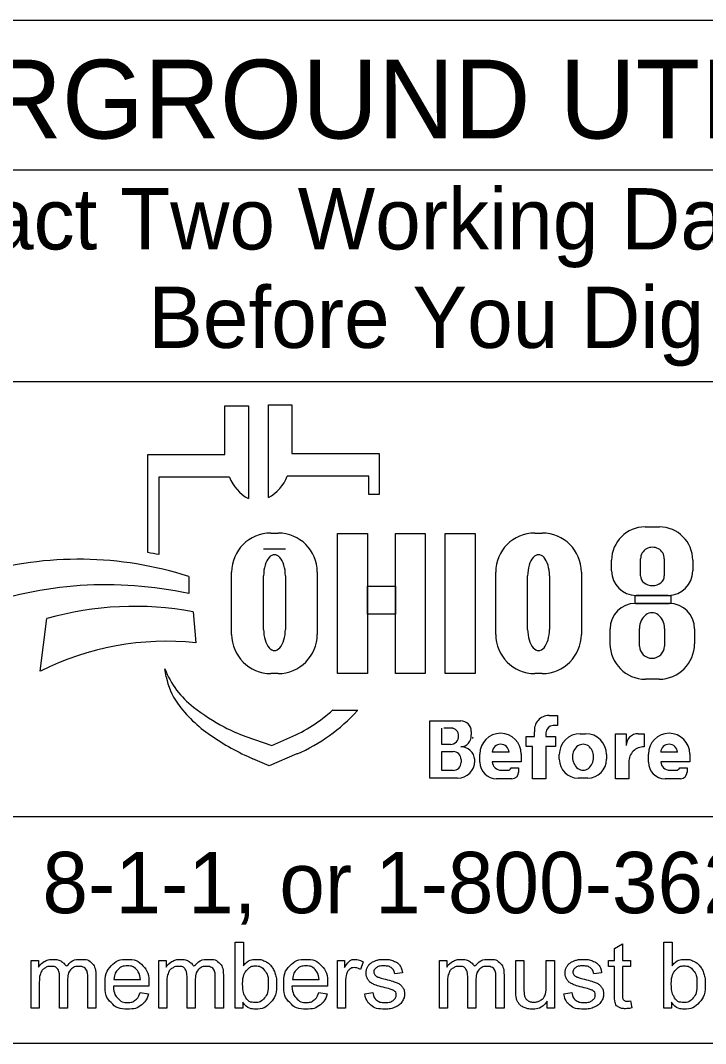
# Model space of a CAD drawing. Extents: x 0 to 34, y 0 to 22.
# Drawn here: x 15.596 to 17.16, y 5.709 to 8.047 of the extents above; entities that cross this region are included whole.
import ezdxf

# ---------------------------------------------------------------- set-up
doc = ezdxf.new("R2010")
doc.units = 0
doc.layers.add('SH_Data', color=7, linetype='Continuous')
doc.layers.add('SH_Text', color=7, linetype='Continuous')

msp = doc.modelspace()

# ---------------------------------------------------------------- linework, layer by layer
at = {"layer": 'SH_Data'}
for p, q in [((18.9567, 8.0466), (14.7067, 8.0466)), ((14.7067, 7.7051), (18.9567, 7.7051)), ((14.7067, 7.2217), (18.9567, 7.2217)), ((18.9567, 6.227), (14.7067, 6.227)), ((18.9567, 5.7091), (14.7067, 5.7091))]:
    msp.add_line(p, q, dxfattribs=at)
at = {"layer": 'SH_Text'}
for p, q in [((16.0627, 7.0547), (16.0627, 7.1661)), ((16.0627, 7.1661), (16.1163, 7.1661)), ((16.1163, 7.1661), (16.1163, 6.9541)), ((16.162, 6.9564), (16.162, 7.1685)), ((16.162, 7.1685), (16.2157, 7.1685)), ((16.2157, 7.1685), (16.2157, 7.057)), ((15.8867, 6.8308), (15.8867, 7.0547)), ((15.8867, 7.0547), (16.0627, 7.0547)), ((16.2157, 7.057), (16.4149, 7.057)), ((16.4149, 7.057), (16.4149, 6.9632)), ((15.912, 7.0032), (15.912, 6.8264)), ((16.0731, 7.0032), (15.912, 7.0032)), ((16.3916, 7.0055), (16.2052, 7.0055)), ((16.3916, 6.9632), (16.3916, 7.0055)), ((16.4149, 6.9632), (16.3916, 6.9632)), ((16.1677, 6.8755), (16.1842, 6.8755)), ((16.7707, 6.8755), (16.7873, 6.8755)), ((17.0223, 6.8895), (17.055, 6.8895)), ((16.201, 6.8385), (16.1512, 6.8385)), ((16.946, 6.7889), (16.946, 6.8132)), ((17.0121, 6.7775), (17.0121, 6.8168)), ((17.0663, 6.8168), (17.0663, 6.7775)), ((17.1313, 6.8132), (17.1313, 6.7889)), ((16.0782, 6.644), (16.0782, 6.786)), ((16.2737, 6.786), (16.2737, 6.644)), ((16.6813, 6.644), (16.6813, 6.786)), ((16.8768, 6.786), (16.8768, 6.644)), ((15.9801, 6.7761), (15.9801, 6.7373)), ((16.1511, 6.6554), (16.1511, 6.7777)), ((16.2009, 6.7777), (16.2009, 6.6554)), ((16.7542, 6.6554), (16.7542, 6.7777)), ((16.804, 6.7777), (16.804, 6.6554)), ((17.0753, 6.7329), (17.002, 6.7329)), ((17.0002, 6.7146), (17.0775, 6.7146)), ((15.99, 6.6955), (15.9962, 6.6245)), ((15.6412, 6.5599), (15.6559, 6.6801)), ((16.9423, 6.6226), (16.9423, 6.6567)), ((17.0098, 6.6167), (17.0098, 6.6576)), ((17.0666, 6.6576), (17.0666, 6.6167)), ((17.1354, 6.6567), (17.1354, 6.6226)), ((15.9289, 6.547), (15.9259, 6.565)), ((16.1842, 6.5545), (16.1677, 6.5545)), ((16.7873, 6.5545), (16.7707, 6.5545)), ((17.0544, 6.5417), (17.0232, 6.5417)), ((16.3092, 6.4712), (16.3666, 6.4712)), ((16.8031, 6.4589), (16.8225, 6.4589)), ((16.8225, 6.4589), (16.8225, 6.4359)), ((16.5305, 6.3154), (16.5305, 6.4461)), ((16.5305, 6.4461), (16.6017, 6.4461)), ((16.5585, 6.3926), (16.5585, 6.4296)), ((16.5837, 6.4296), (16.5624, 6.4296)), ((16.8225, 6.4355), (16.8124, 6.4355)), ((16.1108, 6.4108), (16.1702, 6.3903)), ((16.1702, 6.3903), (16.2112, 6.4081)), ((16.6254, 6.4224), (16.6254, 6.4145)), ((16.7505, 6.3876), (16.7505, 6.4105)), ((16.7505, 6.4105), (16.7698, 6.4105)), ((16.7698, 6.4105), (16.7698, 6.421)), ((16.7959, 6.419), (16.7959, 6.4105)), ((16.7959, 6.4105), (16.8175, 6.4105)), ((16.8175, 6.4105), (16.8175, 6.3876)), ((16.8743, 6.4171), (16.8864, 6.4171)), ((16.9545, 6.3142), (16.9545, 6.4169)), ((16.9545, 6.4169), (16.9791, 6.4169)), ((16.9791, 6.4169), (16.9791, 6.39)), ((17.0063, 6.4169), (17.0202, 6.4169)), ((17.0202, 6.4169), (17.0202, 6.3872)), ((16.5779, 6.3926), (16.5585, 6.3926)), ((16.7654, 6.3876), (16.7505, 6.3876)), ((16.7654, 6.3142), (16.7654, 6.3876)), ((16.8175, 6.3876), (16.7959, 6.3876)), ((16.7959, 6.3876), (16.7959, 6.3142)), ((16.1642, 6.3433), (16.1268, 6.3597)), ((16.2274, 6.3707), (16.1642, 6.3433)), ((16.5585, 6.3332), (16.5585, 6.3761)), ((16.5585, 6.3761), (16.584, 6.3761)), ((16.645, 6.3522), (16.645, 6.3706)), ((16.7116, 6.3746), (16.6731, 6.3746)), ((16.7396, 6.3706), (16.7396, 6.3529)), ((16.8265, 6.3585), (16.8265, 6.3693)), ((16.9342, 6.3693), (16.9342, 6.3585)), ((17.03, 6.3522), (17.03, 6.3706)), ((17.0965, 6.3746), (17.058, 6.3746)), ((17.1245, 6.3706), (17.1245, 6.3529)), ((16.6021, 6.358), (16.6021, 6.3516)), ((16.6335, 6.3551), (16.6335, 6.3547)), ((16.7396, 6.3529), (16.6731, 6.3529)), ((16.7168, 6.3392), (16.7336, 6.3392)), ((16.7336, 6.3392), (16.7336, 6.3294)), ((16.9851, 6.3523), (16.9851, 6.3142)), ((17.1245, 6.3529), (17.0581, 6.3529)), ((17.1017, 6.3392), (17.1186, 6.3392)), ((17.1186, 6.3392), (17.1186, 6.3294)), ((16.5942, 6.3154), (16.5305, 6.3154)), ((16.5837, 6.3332), (16.5585, 6.3332)), ((16.7184, 6.3142), (16.683, 6.3142)), ((16.6941, 6.3337), (16.7082, 6.3337)), ((16.7959, 6.3142), (16.7654, 6.3142)), ((16.8915, 6.3157), (16.8693, 6.3157)), ((16.9851, 6.3142), (16.9545, 6.3142)), ((17.1033, 6.3142), (17.0679, 6.3142)), ((17.079, 6.3337), (17.0931, 6.3337))]:
    msp.add_line(p, q, dxfattribs=at)
for points in [[(16.3201, 6.8744), (16.3881, 6.8744), (16.3881, 6.5544), (16.3201, 6.5544)], [(16.4523, 6.8744), (16.5202, 6.8744), (16.5202, 6.5544), (16.4523, 6.5544)], [(16.5656, 6.8744), (16.6344, 6.8744), (16.6344, 6.5544), (16.5656, 6.5544)], [(16.3881, 6.7545), (16.4523, 6.7545), (16.4523, 6.6905), (16.3881, 6.6905)], [(16.9998, 6.7329), (17.0815, 6.7329), (17.0815, 6.7144), (16.9998, 6.7144)]]:
    msp.add_lwpolyline(points, close=True, dxfattribs=at)
for points in [[(16.1035, 5.7903), (16.0865, 5.7903), (16.0865, 5.9404), (16.1049, 5.9404), (16.1049, 5.8869)], [(17.0826, 5.7903), (17.0655, 5.7903), (17.0655, 5.9404), (17.0839, 5.9404), (17.0839, 5.8869)], [(16.9524, 5.8221), (16.9524, 5.8848), (16.9388, 5.8848), (16.9388, 5.8991), (16.9524, 5.8991), (16.9524, 5.9261), (16.9709, 5.9371), (16.9709, 5.8991), (16.9893, 5.8991), (16.9893, 5.8848), (16.9709, 5.8848), (16.9709, 5.821)], [(15.6204, 5.7903), (15.6204, 5.8991), (15.6369, 5.8991), (15.6369, 5.8838)], [(15.9118, 5.7903), (15.9118, 5.8991), (15.9283, 5.8991), (15.9283, 5.8838)], [(16.3196, 5.7903), (16.3196, 5.8991), (16.3362, 5.8991), (16.3362, 5.8826)], [(16.3786, 5.8956), (16.3722, 5.8786)], [(16.5528, 5.7903), (16.5528, 5.8991), (16.5693, 5.8991), (16.5693, 5.8838)], [(16.7271, 5.8317), (16.7271, 5.8991), (16.7455, 5.8991), (16.7455, 5.8388)], [(16.7968, 5.8408), (16.7968, 5.8991), (16.8152, 5.8991), (16.8152, 5.7903), (16.7987, 5.7903)], [(16.4686, 5.871), (16.4505, 5.8686)], [(16.9231, 5.871), (16.9051, 5.8686)], [(15.6388, 5.8467), (15.6388, 5.7903), (15.6204, 5.7903)], [(15.7035, 5.8534), (15.7035, 5.7903), (15.6851, 5.7903), (15.6851, 5.8609)], [(15.7679, 5.8649), (15.7679, 5.7903), (15.7495, 5.7903), (15.7495, 5.8588)], [(15.809, 5.8551), (15.8698, 5.8551)], [(15.9302, 5.8467), (15.9302, 5.7903), (15.9118, 5.7903)], [(15.9949, 5.8534), (15.9949, 5.7903), (15.9765, 5.7903), (15.9765, 5.8609)], [(16.0593, 5.8649), (16.0593, 5.7903), (16.0409, 5.7903), (16.0409, 5.8588)], [(16.217, 5.8551), (16.2778, 5.8551)], [(16.338, 5.8473), (16.338, 5.7903), (16.3196, 5.7903)], [(16.5712, 5.8467), (16.5712, 5.7903), (16.5528, 5.7903)], [(16.6359, 5.8534), (16.6359, 5.7903), (16.6174, 5.7903), (16.6174, 5.8609)], [(16.7003, 5.8649), (16.7003, 5.7903), (16.6819, 5.7903), (16.6819, 5.8588)], [(15.8892, 5.8399), (15.808, 5.8399)], [(15.8696, 5.8254), (15.8886, 5.823)], [(16.2972, 5.8399), (16.216, 5.8399)], [(16.2776, 5.8254), (16.2966, 5.823)], [(16.3822, 5.8228), (16.4004, 5.8256)], [(16.8367, 5.8228), (16.8549, 5.8256)], [(16.1035, 5.8039), (16.1035, 5.7903)], [(16.7987, 5.7903), (16.7987, 5.8063)], [(16.9893, 5.8067), (16.9919, 5.7904)], [(17.0826, 5.8039), (17.0826, 5.7903)]]:
    msp.add_lwpolyline(points, dxfattribs=at)
for centre, radius, start, end in [((16.1645, 7.04), 0.0985, 201.9296, 240.7469), ((16.1139, 7.0423), 0.0985, 299.2531, 338.0704), ((16.1677, 6.786), 0.0895, 90, 180), ((16.1842, 6.786), 0.0895, 0, 90), ((16.7707, 6.786), 0.0895, 90, 180), ((16.7873, 6.786), 0.0895, 0, 90), ((17.0223, 6.8132), 0.0763, 90, 180), ((17.055, 6.8132), 0.0763, 0, 90), ((15.7586, 6.0218), 0.8191, 79.2074, 81.0007), ((15.7289, 5.9965), 0.8191, 72.1402, 106.3144), ((17.002, 6.7889), 0.056, 180, 270), ((17.0753, 6.7889), 0.056, 270, 0), ((15.7919, 5.8654), 0.8919, 77.8238, 109.8274), ((17.0002, 6.6567), 0.0579, 90, 180), ((17.0775, 6.6567), 0.0579, 0, 90), ((15.8558, 5.9757), 0.7322, 79.44, 105.8467), ((16.1677, 6.644), 0.0895, 180, 270), ((16.1842, 6.644), 0.0895, 270, 0), ((16.7707, 6.644), 0.0895, 180, 270), ((16.7873, 6.644), 0.0895, 270, 0), ((15.9279, 5.9925), 0.6357, 83.8248, 116.8021), ((17.0232, 6.6226), 0.081, 180, 270), ((17.0544, 6.6226), 0.081, 270, 0), ((16.1132, 6.6371), 0.2008, 201.0457, 232.5314), ((16.0702, 6.5711), 0.1433, 189.6817, 216.0884), ((16.2039, 6.6686), 0.3088, 216.0884, 235.7167), ((16.3058, 6.8883), 0.5173, 232.5314, 241.794), ((16.0678, 6.7386), 0.3602, 293.4582, 312.0712), ((16.0678, 6.7386), 0.401, 293.4582, 317.8286), ((16.8031, 6.4254), 0.0335, 90, 187.5187), ((16.2206, 6.7295), 0.3371, 241.794, 250.9821), ((16.5797, 6.4127), 0.0169, 357.8325, 90), ((16.6017, 6.4224), 0.0238, 0, 90), ((16.8124, 6.419), 0.0165, 90, 180), ((16.3704, 6.9128), 0.6044, 235.7167, 246.2325), ((16.5779, 6.4114), 0.0187, 270, 2.0582), ((16.6013, 6.4116), 0.0243, 270, 6.6529), ((16.6119, 6.4102), 0.0175, 347.4023, 0), ((16.6923, 6.3706), 0.0473, 0, 180), ((16.8743, 6.3693), 0.0478, 90, 180), ((16.8864, 6.3693), 0.0478, 0, 90), ((17.006, 6.39), 0.0269, 89.2449, 180), ((17.0772, 6.3706), 0.0473, 0, 180), ((16.6014, 6.3552), 0.0321, 4.0748, 90), ((16.6924, 6.3736), 0.0193, 2.9632, 177.0368), ((17.02, 6.3523), 0.0349, 89.6033, 180), ((17.0773, 6.3736), 0.0193, 2.9632, 177.0368), ((16.584, 6.358), 0.0181, 0, 90), ((16.6005, 6.3551), 0.033, 0, 11.7502), ((16.8693, 6.3585), 0.0428, 180, 270), ((16.8915, 6.3585), 0.0428, 270, 0), ((16.5837, 6.3516), 0.0184, 270, 0), ((16.5942, 6.3547), 0.0393, 270, 0), ((16.683, 6.3522), 0.038, 180, 270), ((16.6941, 6.3547), 0.021, 184.827, 270), ((16.7082, 6.3431), 0.00938, 270, 335.9979), ((17.0679, 6.3522), 0.038, 180, 270), ((17.079, 6.3547), 0.021, 184.827, 270), ((17.0931, 6.3431), 0.00938, 270, 335.9979), ((16.7184, 6.3294), 0.0152, 270, 0), ((17.1033, 6.3294), 0.0152, 270, 0)]:
    msp.add_arc(centre, radius, start, end, dxfattribs=at)
for centre, major_axis, ratio, start_param, end_param in [((16.176, 6.7777), (0, 0.0484), 0.514403, 4.712389, 7.853982), ((16.7791, 6.7777), (0, 0.0484), 0.514403, 4.712389, 7.853982), ((17.0392, 6.8168), (0.0271, 0), 0.969373, 0, 3.141593), ((17.0392, 6.7775), (0.0271, 0), 0.818453, 3.141593, 6.283185), ((17.0382, 6.6576), (0, 0.0358), 0.794529, 4.712389, 7.853982), ((16.176, 6.6554), (0, 0.0484), 0.514403, 1.570796, 4.712389), ((16.7791, 6.6554), (0, 0.0484), 0.514403, 1.570796, 4.712389), ((17.0382, 6.6167), (0.0284, 0), 0.959837, 3.141593, 6.283185), ((16.8808, 6.3639), (0, 0.029), 0.832186, 4.712389, 7.853982), ((16.8808, 6.3639), (0, 0.0302), 0.797287, 1.570796, 4.712389)]:
    msp.add_ellipse(centre, major_axis=major_axis, ratio=ratio, start_param=start_param, end_param=end_param, dxfattribs=at)
for points in [[(15.6369, 5.8838), (15.642, 5.8918), (15.6505, 5.8966), (15.659, 5.9015), (15.6699, 5.9015), (15.682, 5.9015), (15.6897, 5.8965), (15.6975, 5.8915), (15.7006, 5.8824), (15.7136, 5.9015), (15.7343, 5.9015), (15.7505, 5.9015), (15.7592, 5.8926), (15.7679, 5.8836), (15.7679, 5.8649)], [(15.8886, 5.823), (15.8841, 5.8063), (15.872, 5.7971), (15.8598, 5.7879), (15.8408, 5.7879), (15.817, 5.7879), (15.803, 5.8026), (15.789, 5.8173), (15.789, 5.8438), (15.789, 5.8712), (15.8031, 5.8864), (15.8173, 5.9015), (15.8398, 5.9015), (15.8616, 5.9015), (15.8754, 5.8867), (15.8893, 5.8718), (15.8893, 5.8449), (15.8893, 5.8432), (15.8892, 5.8399)], [(15.9283, 5.8838), (15.9334, 5.8918), (15.9419, 5.8966), (15.9504, 5.9015), (15.9613, 5.9015), (15.9734, 5.9015), (15.9811, 5.8965), (15.9888, 5.8915), (15.992, 5.8824), (16.0049, 5.9015), (16.0257, 5.9015), (16.0419, 5.9015), (16.0506, 5.8926), (16.0593, 5.8836), (16.0593, 5.8649)], [(16.1049, 5.8869), (16.1165, 5.9015), (16.1347, 5.9015), (16.1447, 5.9015), (16.1537, 5.8975), (16.1626, 5.8934), (16.1684, 5.8861), (16.1742, 5.8788), (16.1775, 5.8684), (16.1808, 5.8581), (16.1808, 5.8463), (16.1808, 5.8184), (16.1669, 5.8031), (16.1531, 5.7879), (16.1337, 5.7879), (16.1145, 5.7879), (16.1035, 5.8039)], [(16.2966, 5.823), (16.2921, 5.8063), (16.2799, 5.7971), (16.2678, 5.7879), (16.2488, 5.7879), (16.225, 5.7879), (16.211, 5.8026), (16.197, 5.8173), (16.197, 5.8438), (16.197, 5.8712), (16.2111, 5.8864), (16.2253, 5.9015), (16.2478, 5.9015), (16.2696, 5.9015), (16.2834, 5.8867), (16.2973, 5.8718), (16.2973, 5.8449), (16.2973, 5.8432), (16.2972, 5.8399)], [(16.3362, 5.8826), (16.3425, 5.8942), (16.3479, 5.8978), (16.3533, 5.9015), (16.3597, 5.9015), (16.369, 5.9015), (16.3786, 5.8956)], [(16.4004, 5.8256), (16.4019, 5.8147), (16.4089, 5.8088), (16.416, 5.803), (16.4286, 5.803), (16.4414, 5.803), (16.4475, 5.8082), (16.4537, 5.8133), (16.4537, 5.8203), (16.4537, 5.8266), (16.4482, 5.8302), (16.4444, 5.8326), (16.4294, 5.8364), (16.4091, 5.8415), (16.4012, 5.8453), (16.3934, 5.849), (16.3893, 5.8556), (16.3853, 5.8622), (16.3853, 5.8702), (16.3853, 5.8775), (16.3886, 5.8837), (16.3919, 5.8898), (16.3977, 5.8939), (16.402, 5.8971), (16.4094, 5.8993), (16.4169, 5.9015), (16.4254, 5.9015), (16.4382, 5.9015), (16.4479, 5.8978), (16.4576, 5.8941), (16.4622, 5.8878), (16.4668, 5.8815), (16.4686, 5.871)], [(16.5693, 5.8838), (16.5744, 5.8918), (16.5829, 5.8966), (16.5914, 5.9015), (16.6023, 5.9015), (16.6144, 5.9015), (16.6221, 5.8965), (16.6298, 5.8915), (16.633, 5.8824), (16.6459, 5.9015), (16.6667, 5.9015), (16.6829, 5.9015), (16.6916, 5.8926), (16.7003, 5.8836), (16.7003, 5.8649)], [(16.8549, 5.8256), (16.8565, 5.8147), (16.8635, 5.8088), (16.8706, 5.803), (16.8832, 5.803), (16.8959, 5.803), (16.9021, 5.8082), (16.9083, 5.8133), (16.9083, 5.8203), (16.9083, 5.8266), (16.9028, 5.8302), (16.899, 5.8326), (16.8839, 5.8364), (16.8636, 5.8415), (16.8558, 5.8453), (16.8479, 5.849), (16.8439, 5.8556), (16.8398, 5.8622), (16.8398, 5.8702), (16.8398, 5.8775), (16.8432, 5.8837), (16.8465, 5.8898), (16.8522, 5.8939), (16.8566, 5.8971), (16.864, 5.8993), (16.8714, 5.9015), (16.88, 5.9015), (16.8928, 5.9015), (16.9025, 5.8978), (16.9122, 5.8941), (16.9168, 5.8878), (16.9214, 5.8815), (16.9231, 5.871)], [(17.0839, 5.8869), (17.0956, 5.9015), (17.1137, 5.9015), (17.1238, 5.9015), (17.1327, 5.8975), (17.1417, 5.8934), (17.1475, 5.8861), (17.1533, 5.8788), (17.1565, 5.8684), (17.1598, 5.8581), (17.1598, 5.8463), (17.1598, 5.8184), (17.146, 5.8031), (17.1322, 5.7879), (17.1128, 5.7879), (17.0935, 5.7879), (17.0826, 5.8039)], [(15.6851, 5.8609), (15.6851, 5.8732), (15.6806, 5.8794), (15.6761, 5.8855), (15.6658, 5.8855), (15.658, 5.8855), (15.6514, 5.8814), (15.6448, 5.8773), (15.6418, 5.8694), (15.6388, 5.8615), (15.6388, 5.8467)], [(15.7495, 5.8588), (15.7495, 5.8698), (15.7477, 5.8747), (15.7459, 5.8796), (15.7412, 5.8825), (15.7365, 5.8855), (15.7301, 5.8855), (15.7187, 5.8855), (15.7111, 5.8779), (15.7035, 5.8702), (15.7035, 5.8534)], [(15.8698, 5.8551), (15.8686, 5.8688), (15.8628, 5.8757), (15.854, 5.8864), (15.84, 5.8864), (15.8273, 5.8864), (15.8186, 5.8779), (15.81, 5.8693), (15.809, 5.8551)], [(15.9765, 5.8609), (15.9765, 5.8732), (15.9719, 5.8794), (15.9674, 5.8855), (15.9572, 5.8855), (15.9494, 5.8855), (15.9428, 5.8814), (15.9362, 5.8773), (15.9332, 5.8694), (15.9302, 5.8615), (15.9302, 5.8467)], [(16.0409, 5.8588), (16.0409, 5.8698), (16.0391, 5.8747), (16.0373, 5.8796), (16.0326, 5.8825), (16.0279, 5.8855), (16.0215, 5.8855), (16.01, 5.8855), (16.0025, 5.8779), (15.9949, 5.8702), (15.9949, 5.8534)], [(16.1033, 5.8455), (16.1033, 5.8259), (16.1086, 5.8172), (16.1173, 5.803), (16.1321, 5.803), (16.1442, 5.803), (16.153, 5.8135), (16.1618, 5.824), (16.1618, 5.8448), (16.1618, 5.8661), (16.1533, 5.8763), (16.1449, 5.8864), (16.1329, 5.8864), (16.1209, 5.8864), (16.1121, 5.8759), (16.1033, 5.8654), (16.1033, 5.8455)], [(16.2778, 5.8551), (16.2766, 5.8688), (16.2708, 5.8757), (16.262, 5.8864), (16.248, 5.8864), (16.2353, 5.8864), (16.2266, 5.8779), (16.218, 5.8693), (16.217, 5.8551)], [(16.3722, 5.8786), (16.3654, 5.8825), (16.3587, 5.8825), (16.3527, 5.8825), (16.3479, 5.8789), (16.3431, 5.8752), (16.3411, 5.8688), (16.338, 5.8589), (16.338, 5.8473)], [(16.4505, 5.8686), (16.4493, 5.877), (16.4434, 5.8817), (16.4375, 5.8864), (16.4267, 5.8864), (16.414, 5.8864), (16.4086, 5.8822), (16.4031, 5.878), (16.4031, 5.8724), (16.4031, 5.8688), (16.4054, 5.8659), (16.4076, 5.8629), (16.4124, 5.861), (16.4152, 5.8599), (16.4288, 5.8562), (16.4483, 5.851), (16.4561, 5.8477), (16.4639, 5.8444), (16.4683, 5.838), (16.4727, 5.8317), (16.4727, 5.8223), (16.4727, 5.8131), (16.4673, 5.8049), (16.4619, 5.7968), (16.4518, 5.7923), (16.4416, 5.7879), (16.4288, 5.7879), (16.4075, 5.7879), (16.3964, 5.7967), (16.3853, 5.8055), (16.3822, 5.8228)], [(16.6174, 5.8609), (16.6174, 5.8732), (16.6129, 5.8794), (16.6084, 5.8855), (16.5982, 5.8855), (16.5904, 5.8855), (16.5838, 5.8814), (16.5772, 5.8773), (16.5742, 5.8694), (16.5712, 5.8615), (16.5712, 5.8467)], [(16.6819, 5.8588), (16.6819, 5.8698), (16.6801, 5.8747), (16.6783, 5.8796), (16.6736, 5.8825), (16.6689, 5.8855), (16.6625, 5.8855), (16.651, 5.8855), (16.6435, 5.8779), (16.6359, 5.8702), (16.6359, 5.8534)], [(16.9051, 5.8686), (16.9038, 5.877), (16.8979, 5.8817), (16.892, 5.8864), (16.8813, 5.8864), (16.8686, 5.8864), (16.8631, 5.8822), (16.8577, 5.878), (16.8577, 5.8724), (16.8577, 5.8688), (16.8599, 5.8659), (16.8622, 5.8629), (16.867, 5.861), (16.8698, 5.8599), (16.8833, 5.8562), (16.9029, 5.851), (16.9107, 5.8477), (16.9184, 5.8444), (16.9228, 5.838), (16.9273, 5.8317), (16.9273, 5.8223), (16.9273, 5.8131), (16.9219, 5.8049), (16.9165, 5.7968), (16.9063, 5.7923), (16.8962, 5.7879), (16.8833, 5.7879), (16.8621, 5.7879), (16.851, 5.7967), (16.8398, 5.8055), (16.8367, 5.8228)], [(17.0823, 5.8455), (17.0823, 5.8259), (17.0877, 5.8172), (17.0963, 5.803), (17.1112, 5.803), (17.1232, 5.803), (17.132, 5.8135), (17.1408, 5.824), (17.1408, 5.8448), (17.1408, 5.8661), (17.1324, 5.8763), (17.1239, 5.8864), (17.112, 5.8864), (17.0999, 5.8864), (17.0911, 5.8759), (17.0823, 5.8654), (17.0823, 5.8455)], [(15.808, 5.8399), (15.809, 5.822), (15.8182, 5.8125), (15.8273, 5.803), (15.8409, 5.803), (15.8511, 5.803), (15.8582, 5.8083), (15.8654, 5.8137), (15.8696, 5.8254)], [(16.216, 5.8399), (16.217, 5.822), (16.2261, 5.8125), (16.2353, 5.803), (16.2489, 5.803), (16.259, 5.803), (16.2662, 5.8083), (16.2734, 5.8137), (16.2776, 5.8254)], [(16.7987, 5.8063), (16.7861, 5.7879), (16.7643, 5.7879), (16.7546, 5.7879), (16.7463, 5.7916), (16.738, 5.7952), (16.7339, 5.8008), (16.7299, 5.8064), (16.7282, 5.8145), (16.7271, 5.8199), (16.7271, 5.8317)], [(16.7455, 5.8388), (16.7455, 5.8244), (16.7467, 5.8193), (16.7484, 5.8121), (16.754, 5.8079), (16.7597, 5.8038), (16.7679, 5.8038), (16.7762, 5.8038), (16.7835, 5.808), (16.7908, 5.8123), (16.7938, 5.8196), (16.7968, 5.8269), (16.7968, 5.8408)], [(16.9919, 5.7904), (16.9842, 5.7888), (16.978, 5.7888), (16.968, 5.7888), (16.9625, 5.792), (16.9569, 5.7951), (16.9547, 5.8003), (16.9524, 5.8055), (16.9524, 5.8221)], [(16.9709, 5.821), (16.9709, 5.8131), (16.9718, 5.8109), (16.9728, 5.8086), (16.975, 5.8073), (16.9772, 5.806), (16.9813, 5.806), (16.9843, 5.806), (16.9893, 5.8067)]]:
    msp.add_open_spline(points, degree=3, dxfattribs=at)

# ---------------------------------------------------------------- texts
for s, height, p in [('UNDERGROUND UTILITIES', 0.18, (14.8348, 7.777)), ('Contact Two Working Days', 0.14, (15.1263, 7.5235)), ('Before You Dig', 0.14, (15.8875, 7.2985)), ('OHIO811, 8-1-1, or 1-800-362-2764', 0.14, (14.7511, 6.007))]:
    msp.add_text(s, height=height, dxfattribs=at).set_placement(p)

doc.saveas('drawing.dxf')
